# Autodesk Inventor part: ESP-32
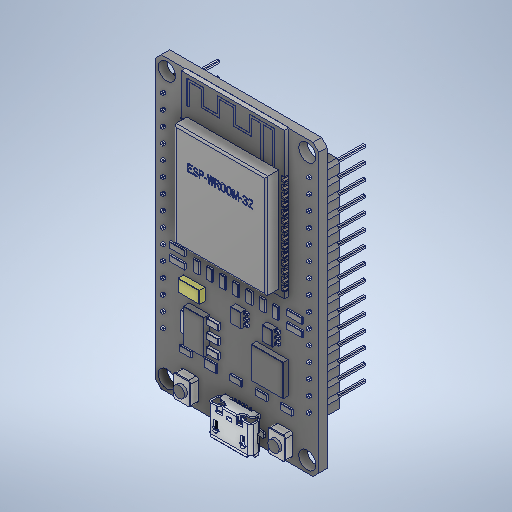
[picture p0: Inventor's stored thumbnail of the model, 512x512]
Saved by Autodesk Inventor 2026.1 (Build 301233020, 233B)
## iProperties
Created: 1705-05
Part Number: ESP-32
Material: Generic
Document SubType Name: Modeling
Designer: hp
Density: 1 g/cm^3
Appearance: Default
Author: hp
Sending System: SOLIDWORKS 2021
Last Saved Date: 1601-01-01
last saved by: Vivek
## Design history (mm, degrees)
feature "6.ESP-32-1-solid1"
feature "micro_usb_47346-0001-1-solid1"
feature "ESP-WROOM-32-1-solid1"
body "Solid1"
body "Solid2"
body "Solid3"
